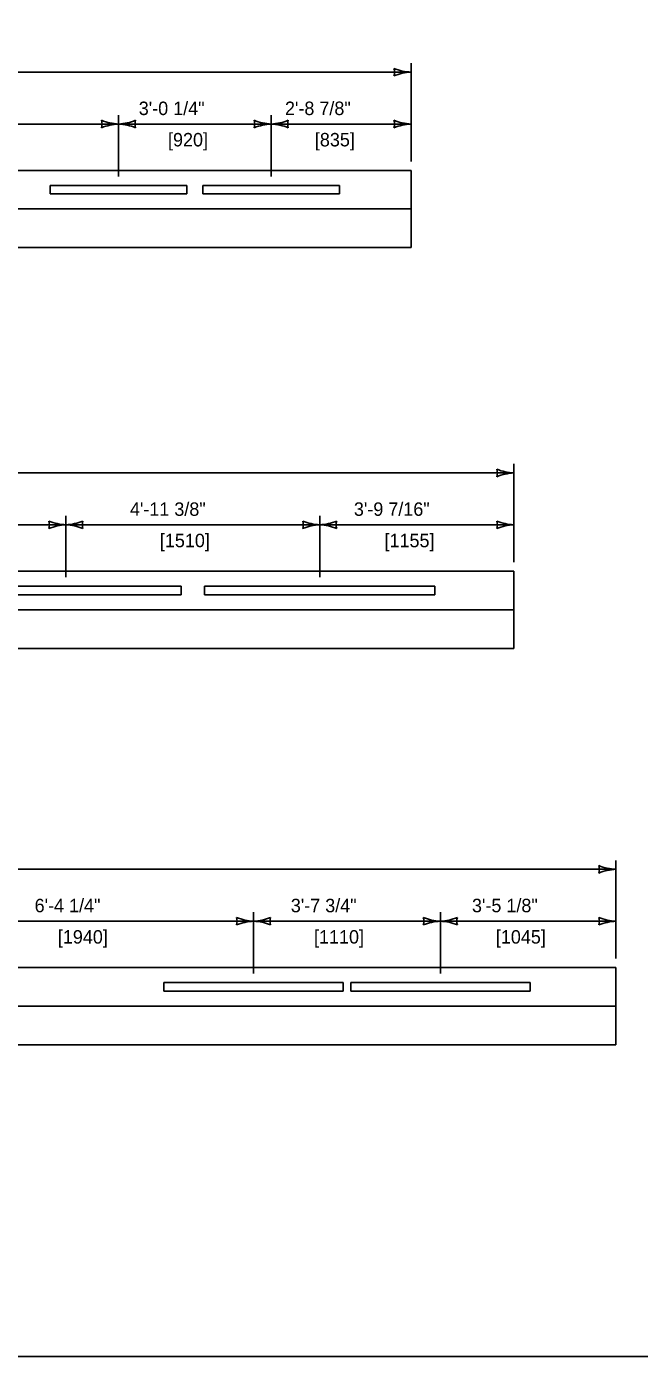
# Model space of a CAD drawing. Extents: x 49991.4 to 50021, y 49987.6 to 50011.4.
# Drawn here: x 50006.69 to 50009.43, y 49987.8 to 49993.74 of the extents above; entities that cross this region are included whole.
import ezdxf

# ---------------------------------------------------------------- set-up
doc = ezdxf.new("R2010")
doc.units = 0
for name, color, linetype in [('Level 1', 7, 'Continuous'), ('Level 2', 7, 'Continuous'), ('Level 3', 7, 'Continuous'), ('Level 5', 7, 'Continuous')]:
    doc.layers.add(name, color=color, linetype=linetype)

msp = doc.modelspace()

# ---------------------------------------------------------------- linework, layer by layer
at = {"layer": 'Level 1'}
for p, q in [((50000.9788, 49993.0937), (50008.4087, 49993.0937)), ((50008.4087, 49993.0937), (50008.4087, 49992.7487)), ((50007.4086, 49993.0265), (50006.799, 49993.0265)), ((50006.799, 49993.0265), (50006.799, 49992.9884)), ((50007.4086, 49992.9884), (50007.4086, 49993.0265)), ((50008.0899, 49993.0265), (50007.4803, 49993.0265)), ((50007.4803, 49993.0265), (50007.4803, 49992.9884)), ((50008.0899, 49992.9884), (50008.0899, 49993.0265)), ((50006.799, 49992.9884), (50007.4086, 49992.9884)), ((50007.4803, 49992.9884), (50008.0899, 49992.9884)), ((50008.4087, 49992.9212), (50000.9788, 49992.9212)), ((50000.9788, 49992.7487), (50008.4087, 49992.7487)), ((50008.8676, 49991.3045), (50000.5199, 49991.3045)), ((50008.8676, 49991.132), (50008.8676, 49991.3045)), ((50007.3825, 49991.2373), (50006.355, 49991.2373)), ((50007.3825, 49991.1991), (50007.3825, 49991.2373)), ((50008.5151, 49991.2373), (50007.4875, 49991.2373)), ((50007.4875, 49991.2373), (50007.4875, 49991.1991)), ((50008.5151, 49991.1991), (50008.5151, 49991.2373)), ((50006.355, 49991.1991), (50007.3825, 49991.1991)), ((50007.4875, 49991.1991), (50008.5151, 49991.1991)), ((50000.5199, 49991.132), (50008.8676, 49991.132)), ((50008.8676, 49990.9594), (50008.8676, 49991.132)), ((50000.5199, 49990.9594), (50008.8676, 49990.9594)), ((50009.3231, 49989.5348), (50000.0644, 49989.5348)), ((50009.3231, 49989.5348), (50009.3231, 49989.1898)), ((50008.1063, 49989.4677), (50007.3062, 49989.4677)), ((50007.3062, 49989.4677), (50007.3062, 49989.4295)), ((50008.1063, 49989.4295), (50008.1063, 49989.4677)), ((50008.9397, 49989.4677), (50008.1396, 49989.4677)), ((50008.1396, 49989.4677), (50008.1396, 49989.4295)), ((50008.9397, 49989.4295), (50008.9397, 49989.4677)), ((50007.3062, 49989.4295), (50008.1063, 49989.4295)), ((50008.1396, 49989.4295), (50008.9397, 49989.4295)), ((50009.3231, 49989.3623), (50000.0644, 49989.3623)), ((50000.0644, 49989.1898), (50009.3231, 49989.1898))]:
    msp.add_line(p, q, dxfattribs=at)
msp.add_lwpolyline([(49999.3835, 49998.9992), (50016.7501, 49998.9992), (50016.7501, 49987.7988), (49999.3835, 49987.7988)], close=True, dxfattribs=at)
at = {"layer": 'Level 3'}
for p, q in [((50008.4087, 49993.1337), (50008.4087, 49993.5722)), ((50002.449, 49993.5322), (50008.4087, 49993.5322)), ((50007.1038, 49993.3006), (50005.9566, 49993.3006)), ((50007.7851, 49993.3006), (50007.1038, 49993.3006)), ((50008.4087, 49993.3006), (50007.7851, 49993.3006)), ((50008.8676, 49991.3445), (50008.8676, 49991.7829)), ((50001.6137, 49991.7429), (50008.8676, 49991.7429)), ((50006.8688, 49991.5114), (50005.26, 49991.5114)), ((50008.0013, 49991.5114), (50006.8688, 49991.5114)), ((50008.8676, 49991.5114), (50008.0013, 49991.5114)), ((50009.3231, 49989.5748), (50009.3231, 49990.0133)), ((50000.9974, 49989.9733), (50009.3231, 49989.9733)), ((50007.7062, 49989.7417), (50006.2534, 49989.7417)), ((50008.5397, 49989.7417), (50007.7062, 49989.7417)), ((50009.3231, 49989.7417), (50008.5397, 49989.7417))]:
    msp.add_line(p, q, dxfattribs=at)
for centre, radius, start, end in [((50008.4178, 49993.7543), 0.2223, 247.45601, 267.63952), ((50008.2804, 49993.5322), 0.0548, 342.13882, 17.86118), ((50008.4201, 49993.2995), 0.233, 92.82731, 112.07716), ((50007.113, 49993.5227), 0.2223, 247.45601, 267.63952), ((50006.9756, 49993.3006), 0.0548, 342.13882, 17.86118), ((50007.0923, 49993.5333), 0.233, 272.82731, 292.07716), ((50007.232, 49993.3006), 0.0548, 162.13882, 197.86118), ((50007.7942, 49993.5227), 0.2223, 247.45601, 267.63952), ((50007.6568, 49993.3006), 0.0548, 342.13882, 17.86118), ((50007.7735, 49993.5333), 0.233, 272.83403, 292.08388), ((50007.9133, 49993.3006), 0.0548, 162.14554, 197.8679), ((50008.4178, 49993.5227), 0.2223, 247.46273, 267.64624), ((50008.2804, 49993.3006), 0.0548, 342.14554, 17.8679), ((50007.1153, 49993.0679), 0.233, 92.82731, 112.07716), ((50007.0947, 49993.0784), 0.2223, 67.45601, 87.63952), ((50007.7966, 49993.0679), 0.233, 92.82731, 112.07716), ((50007.7759, 49993.0784), 0.2223, 67.46273, 87.64624), ((50008.4202, 49993.0679), 0.233, 92.83403, 112.08388), ((50008.8767, 49991.965), 0.2223, 247.45601, 267.63952), ((50008.7394, 49991.7429), 0.0548, 342.13882, 17.86118), ((50008.8791, 49991.5102), 0.233, 92.82731, 112.07716), ((50006.8779, 49991.7335), 0.2223, 247.45601, 267.63952), ((50006.7406, 49991.5114), 0.0548, 342.13882, 17.86118), ((50006.8803, 49991.2786), 0.233, 92.82731, 112.07716), ((50006.8573, 49991.7441), 0.233, 272.82731, 292.07716), ((50006.8596, 49991.2892), 0.2223, 67.45601, 87.63952), ((50006.997, 49991.5114), 0.0548, 162.13882, 197.86118), ((50008.0105, 49991.7335), 0.2223, 247.45601, 267.63952), ((50007.8731, 49991.5114), 0.0548, 342.13882, 17.86118), ((50008.0128, 49991.2786), 0.233, 92.82731, 112.07716), ((50007.9898, 49991.7441), 0.233, 272.82731, 292.07716), ((50007.9922, 49991.2892), 0.2223, 67.45601, 87.63952), ((50008.1295, 49991.5114), 0.0548, 162.13882, 197.86118), ((50008.8767, 49991.7335), 0.2223, 247.45601, 267.63952), ((50008.7394, 49991.5114), 0.0548, 342.13882, 17.86118), ((50008.8791, 49991.2786), 0.233, 92.82731, 112.07716), ((50009.3322, 49990.1954), 0.2223, 247.45601, 267.63952), ((50009.1948, 49989.9733), 0.0548, 342.13882, 17.86118), ((50009.3345, 49989.7406), 0.233, 92.82731, 112.07716), ((50007.7154, 49989.9639), 0.2223, 247.45601, 267.63952), ((50007.578, 49989.7417), 0.0548, 342.13882, 17.86118), ((50007.6947, 49989.9744), 0.233, 272.82731, 292.07716), ((50007.8345, 49989.7417), 0.0548, 162.13882, 197.86118), ((50008.5488, 49989.9639), 0.2223, 247.45601, 267.63952), ((50008.4114, 49989.7417), 0.0548, 342.13882, 17.86118), ((50008.5282, 49989.9744), 0.233, 272.82731, 292.07716), ((50008.6679, 49989.7417), 0.0548, 162.13882, 197.86118), ((50009.3322, 49989.9639), 0.2223, 247.45601, 267.63952), ((50009.1948, 49989.7417), 0.0548, 342.13882, 17.86118), ((50007.7177, 49989.509), 0.233, 92.82731, 112.07716), ((50007.6971, 49989.5196), 0.2223, 67.45601, 87.63952), ((50008.5511, 49989.509), 0.233, 92.82731, 112.07716), ((50008.5305, 49989.5196), 0.2223, 67.45601, 87.63952), ((50009.3345, 49989.509), 0.233, 92.82731, 112.07716)]:
    msp.add_arc(centre, radius, start, end, dxfattribs=at)
at = {"layer": 'Level 5'}
for p, q in [((50007.1038, 49993.0665), (50007.1038, 49993.3406)), ((50007.7851, 49993.0665), (50007.7851, 49993.3406)), ((50006.8688, 49991.2773), (50006.8688, 49991.5514)), ((50008.0013, 49991.2773), (50008.0013, 49991.5514)), ((50007.7062, 49989.5077), (50007.7062, 49989.7817)), ((50008.5397, 49989.5083), (50008.5397, 49989.7817))]:
    msp.add_line(p, q, dxfattribs=at)

# ---------------------------------------------------------------- texts
at = {"layer": 'Level 2'}
for s, p in [('3\'-0 1/4"', (50007.1938, 49993.3406)), ('2\'-8 7/8"', (50007.8462, 49993.3406)), ('[920]', (50007.3243, 49993.2006)), ('[835]', (50007.9797, 49993.2006)), ('4\'-11 3/8"', (50007.1544, 49991.5514)), ('3\'-9 7/16"', (50008.1538, 49991.5514)), ('[1510]', (50007.288, 49991.4114)), ('[1155]', (50008.2904, 49991.4114)), ('6\'-4 1/4"', (50006.7292, 49989.7817)), ('3\'-7 3/4"', (50007.8723, 49989.7817)), ('3\'-5 1/8"', (50008.6807, 49989.7817)), ('[1940]', (50006.8328, 49989.6417)), ('[1110]', (50007.9759, 49989.6417)), ('[1045]', (50008.7873, 49989.6417))]:
    msp.add_text(s, height=0.06, dxfattribs=at).set_placement(p)

doc.saveas('drawing.dxf')
